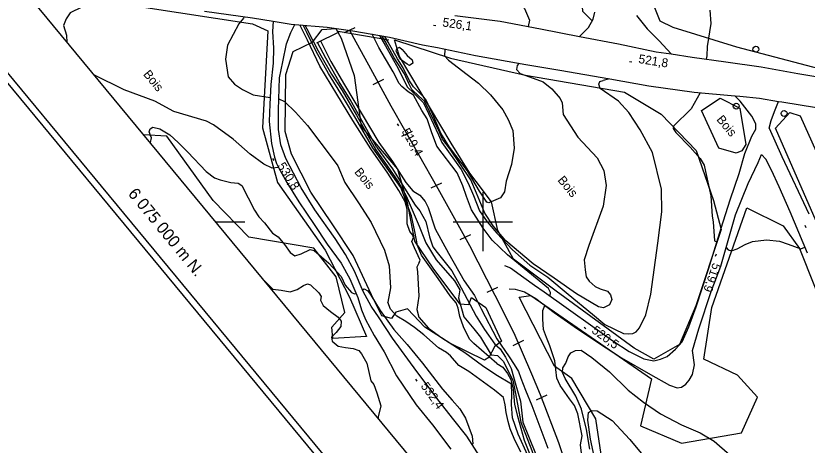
# Model space of a CAD drawing. Extents: x 347312 to 350503, y 6073086 to 6076432.
# Drawn here: x 347542.3 to 347809.5, y 6074924.5 to 6075069.6 of the extents above; entities that cross this region are included whole.
import ezdxf

# ---------------------------------------------------------------- set-up
doc = ezdxf.new("R2010")
doc.units = 0
for name, color, linetype in [('Level 1', 7, 'Continuous'), ('Level 19', 7, 'Continuous'), ('Level 2', 7, 'Continuous'), ('Level 21', 7, 'Continuous'), ('Level 22', 7, 'Continuous'), ('Level 23', 7, 'Continuous'), ('Level 3', 7, 'Continuous'), ('Level 36', 7, 'Continuous'), ('Level 37', 7, 'Continuous'), ('Level 44', 7, 'Continuous'), ('Level 60', 7, 'Continuous'), ('Level 61', 7, 'Continuous')]:
    doc.layers.add(name, color=color, linetype=linetype)

msp = doc.modelspace()

# ---------------------------------------------------------------- linework, layer by layer
at = {"layer": 'Level 1'}
for points in [[(347776.68, 6075071.49), (347777.02, 6075067), (347775.71, 6075059.26)], [(347619.17, 6075068.84), (347617.55, 6075066.91), (347613.79, 6075059.72), (347613.11, 6075054.92), (347613.93, 6075048.96), (347616.11, 6075046.5), (347618.8, 6075044.72), (347622.43, 6075042.93), (347628.18, 6075042.02)], [(347619.41, 6075069.3), (347619.17, 6075068.84)], [(347676.54, 6075042.79), (347674.76, 6075043.96), (347672.59, 6075045.73), (347671.74, 6075046.74), (347669.74, 6075050.69), (347664.91, 6075058.9), (347662.61, 6075063.39)], [(347645.18, 6075061.13), (347648.65, 6075054.15), (347653.21, 6075046.25), (347664.87, 6075026.78), (347669.47, 6075020.39), (347673.93, 6075013.22), (347676.38, 6075010.48), (347678.72, 6075008.98), (347680.56, 6075006.8), (347681.55, 6075004.84), (347683.83, 6074997.57), (347688.41, 6074989.31), (347693.71, 6074980.05), (347697.12, 6074975.06), (347699.43, 6074970.6), (347704.69, 6074960.4), (347708.83, 6074954.28), (347710.61, 6074951.78), (347712, 6074949.34), (347712.87, 6074947.11), (347714.38, 6074943.08), (347716.56, 6074937.87), (347721.93, 6074923.47)], [(347775.71, 6075059.26), (347775.59, 6075056.11), (347775.41, 6075054.99)], [(347773.33, 6075043.59), (347770.36, 6075038.18), (347764.36, 6075032.34), (347764.3, 6075031.5), (347765.2, 6075030.13), (347770, 6075025.24), (347773.43, 6075021.34), (347774.76, 6075019.13), (347775.23, 6075017), (347776.99, 6075008.78), (347777.41, 6075001.82), (347777.76, 6074999.99), (347778.25, 6074993.54), (347779.06, 6074993.15)], [(347631.06, 6075041.57), (347633.05, 6075040.61), (347636.67, 6075037.07), (347640.77, 6075032.47), (347649.49, 6075021.04), (347650.97, 6075018.94), (347653.34, 6075013.2), (347657.94, 6075006.36), (347662.26, 6074999.68), (347666.78, 6074990.41), (347668.35, 6074985.11), (347668.79, 6074977.7), (347667.87, 6074972.83)], [(347722.77, 6074974.78), (347722.86, 6074976.02), (347722.11, 6074977.38), (347715.21, 6074983.17), (347708.3, 6074988.82), (347703.15, 6074993.81), (347700.08, 6074997.76), (347696.12, 6075004.01), (347694.48, 6075008.49), (347693.27, 6075012.13), (347691.32, 6075016.48), (347684.48, 6075025.51), (347682.65, 6075030.36), (347681.15, 6075034.82), (347679.36, 6075037.57), (347676.54, 6075042.79)], [(347782.15, 6074991.29), (347782.89, 6074990.46), (347783.95, 6074990.15), (347785.89, 6074990.85), (347788.62, 6074992.34), (347791.01, 6074993.29), (347795.84, 6074993.88), (347800.21, 6074993.43), (347803.09, 6074992.39), (347807.38, 6074990.88), (347808.79, 6074991.43)], [(347712.78, 6074922.06), (347710.59, 6074926.75), (347709.26, 6074929.93), (347708.49, 6074932.42), (347707.86, 6074935.53), (347707.53, 6074938.11), (347706.97, 6074940.52), (347703.88, 6074943.08), (347695.28, 6074949.34), (347691.86, 6074951.35), (347689.05, 6074954.67), (347687.71, 6074955.79), (347684.96, 6074957.32), (347680.01, 6074961.76), (347676.85, 6074964.25), (347673.93, 6074966.29), (347670.98, 6074968.05), (347668.81, 6074970.46), (347667.87, 6074972.83)], [(347733.3, 6074921.7), (347732.97, 6074924.62), (347733.51, 6074927.6), (347732.12, 6074935.09), (347730.98, 6074937.86), (347729.22, 6074940.1), (347726.05, 6074944.63), (347725.03, 6074947.1), (347724.3, 6074953.01), (347722.63, 6074958), (347721.51, 6074960.82), (347720.49, 6074963.52), (347720.21, 6074967.01), (347720.24, 6074969.97), (347720.94, 6074971.72)]]:
    msp.add_lwpolyline(points, dxfattribs=at)
at = {"layer": 'Level 19'}
for points in [[(347732.67, 6075062.66), (347735.71, 6075065.67), (347737.22, 6075068.49), (347737.84, 6075070.88)], [(347751.92, 6075069.68), (347755.45, 6075065.18), (347759.56, 6075061.15), (347763.54, 6075056.73)], [(347629.21, 6075067.79), (347628.94, 6075064.3), (347629.31, 6075058.61), (347629.18, 6075053.62), (347628.44, 6075046.34), (347628.05, 6075039.79), (347627.83, 6075033.84), (347628.61, 6075026.43), (347629.64, 6075021.82), (347630.25, 6075019.67), (347630.96, 6075018.38), (347633.78, 6075013.22), (347637.86, 6075006.73), (347643.04, 6074999), (347647.4, 6074992.44), (347652.17, 6074985.93), (347655.12, 6074980.7), (347657.73, 6074974.38), (347658.96, 6074970.24), (347660.36, 6074966.98), (347663.32, 6074961.48), (347666.68, 6074956.02), (347670.86, 6074947.92), (347677.45, 6074938.06), (347682.99, 6074931.32), (347689.21, 6074923.15)], [(347699.81, 6074919.34), (347694.59, 6074927.47), (347689.71, 6074933.59), (347685.24, 6074939.31), (347677.66, 6074949.37), (347669.51, 6074960.66), (347664.98, 6074967.51), (347662.32, 6074971.41), (347659.59, 6074976.37), (347656.68, 6074983.32), (347653.64, 6074988.92), (347650.14, 6074994.35), (347643.25, 6075004.04), (347638.61, 6075011.48), (347633.46, 6075021.37), (347631.79, 6075026.04), (347630.92, 6075031.16), (347630.96, 6075037.77), (347631.26, 6075048.67), (347632.44, 6075054.1), (347633.67, 6075060.08), (347635.19, 6075063.94), (347636.53, 6075066.7)], [(347707.25, 6074985.19), (347709.33, 6074984.39), (347713.79, 6074981.1), (347717.39, 6074978.57), (347720.67, 6074976.24), (347728.17, 6074971.01), (347737.97, 6074963.98), (347743.89, 6074959.75), (347749.45, 6074956.12), (347754.34, 6074953.65), (347757.78, 6074953.01), (347759.98, 6074953.58), (347762.22, 6074954.48), (347765.04, 6074956.91), (347767.33, 6074959.34), (347769.59, 6074964.5), (347772.03, 6074971.23), (347776.15, 6074983.99), (347780.53, 6074997.78), (347783.56, 6075007.39), (347786.56, 6075016.24), (347788.43, 6075023.03), (347790.8, 6075028.88), (347792.23, 6075031.27), (347792.23, 6075033.06), (347790.88, 6075035.66), (347786.91, 6075040.78), (347785.04, 6075042.56)], [(347796.73, 6075031.59), (347797.39, 6075034.22), (347798.52, 6075037.25), (347799.17, 6075038.99), (347799.89, 6075040.65)], [(347796.73, 6075031.59), (347800.99, 6075022.01), (347810.06, 6075002.71)], [(347708.87, 6074977.27), (347710.89, 6074977.16), (347714.07, 6074976.31), (347717.89, 6074974.05), (347724.05, 6074969.34), (347731.96, 6074963.79), (347741.62, 6074957.39), (347746.87, 6074953.95), (347756.6, 6074948.35), (347763.02, 6074944.77), (347765.57, 6074943.85), (347767.13, 6074944.03), (347768.57, 6074945.08), (347769.71, 6074946.4), (347770.82, 6074948.37), (347771.52, 6074951.64), (347770.74, 6074956.42), (347772.91, 6074963.83), (347777.15, 6074976.45), (347780.35, 6074984.94), (347782.81, 6074993.63), (347785.35, 6075002.31), (347789.64, 6075012.9), (347793.01, 6075019.96), (347794.13, 6075022.75)], [(347809.66, 6074989.37), (347803.77, 6075003.33), (347800.02, 6075011.84), (347797.52, 6075017.44), (347795.58, 6075021.12), (347794.13, 6075022.75)]]:
    msp.add_lwpolyline(points, dxfattribs=at)
at = {"layer": 'Level 2'}
for points in [[(347693.09, 6075107.08), (347696.94, 6075103.34), (347702.44, 6075093.04), (347704.43, 6075086.79), (347706.07, 6075083.88), (347708.88, 6075077.1), (347712.23, 6075074.08), (347714.07, 6075072.05), (347715.8, 6075068.14), (347715.35, 6075065.99)], [(347729.84, 6075085.22), (347729.61, 6075084.76), (347729.69, 6075083.5), (347732.29, 6075080.61), (347732.83, 6075077.61), (347733.47, 6075074.17), (347733.65, 6075071.14), (347734.85, 6075069.88), (347736.89, 6075067.88)], [(347578.78, 6075075.56), (347576.74, 6075074.61), (347570.99, 6075074), (347564.5, 6075072.51), (347560.66, 6075070.56), (347559.23, 6075068.6), (347558.36, 6075066.29), (347559.36, 6075063.01), (347559.49, 6075060.63)], [(347678.45, 6074986.18), (347678.77, 6074987.03), (347676.86, 6074991.2), (347675.97, 6074993.36), (347676.58, 6074994.67), (347676.36, 6074995.4), (347675.31, 6074996.64), (347674.45, 6074999.23), (347674.45, 6075004.25), (347673.8, 6075006.74), (347671.67, 6075010.51), (347667.86, 6075016.43), (347662.15, 6075024.6), (347656.06, 6075034.16), (347650.73, 6075043.09), (347644.91, 6075052.53), (347640.76, 6075061.36), (347638.18, 6075066.55)], [(347690.93, 6074972.54), (347688.9, 6074974.94), (347684.86, 6074980.82), (347679.25, 6074988.71), (347677.87, 6074991.92), (347676.98, 6074996.73), (347675.85, 6075002), (347672.27, 6075011.58), (347662.81, 6075024.97), (347657.05, 6075034.9), (347652.95, 6075041.92), (347647.85, 6075050.12), (347643.71, 6075057.51), (347640.5, 6075063.93), (347639.29, 6075066.45)], [(347639.92, 6075066.39), (347640.55, 6075065.16), (347644.41, 6075057.8), (347648.88, 6075049.86), (347652.48, 6075044.41), (347657.27, 6075036.07), (347663.82, 6075024.3), (347667.69, 6075018.93), (347671.48, 6075013.35), (347674.12, 6075008.8), (347675.14, 6075006.34), (347675.14, 6075006.34), (347678.44, 6074998.45), (347680.68, 6074992.81), (347684.26, 6074987.1), (347690.38, 6074980.02), (347692.21, 6074976.94), (347691.8, 6074974.22), (347693.61, 6074967.85), (347696.93, 6074963.78), (347699.14, 6074960.95), (347702.83, 6074955.01), (347704.95, 6074954.78), (347706.88, 6074952.82), (347710.13, 6074946.48)], [(347665.11, 6075062.93), (347667.07, 6075059.51), (347671.35, 6075051.8), (347674.45, 6075045.65), (347676.74, 6075043.39), (347680, 6075040.17), (347685.01, 6075029.36)], [(347734.92, 6074981.39), (347735.88, 6074979.94), (347737.89, 6074978.05), (347739.56, 6074977.33), (347742.09, 6074976.53), (347743.14, 6074975.29), (347743.58, 6074973.67), (347742.78, 6074971.94), (347740.71, 6074970.87), (347739.04, 6074971.19), (347731.61, 6074975.57), (347724.05, 6074980.89), (347717.02, 6074985.74), (347707.79, 6074993.52), (347703.46, 6074998.64), (347700.65, 6075002.91), (347697.9, 6075009.62), (347695.97, 6075014.1), (347688.91, 6075024.5), (347686.39, 6075027.95), (347685.36, 6075030.27), (347680.26, 6075040.71), (347678.35, 6075042.39), (347676, 6075044.73), (347675.01, 6075046.72), (347673.48, 6075050), (347670.03, 6075055.44), (347666.96, 6075061.06), (347665.99, 6075062.77)], [(347707.91, 6075013.66), (347707.28, 6075010.07), (347705.98, 6075008.08), (347702.03, 6075006.38), (347701.28, 6075006.63), (347698.85, 6075010.29), (347694.75, 6075017.17), (347688.74, 6075025.24), (347685.85, 6075029.97), (347683.07, 6075036.21), (347680.69, 6075041.32), (347679.83, 6075042.35), (347676.54, 6075045.65), (347675.26, 6075047.67), (347673.11, 6075052.03), (347671.12, 6075055.06), (347667.98, 6075060.75), (347666.91, 6075062.6)], [(347664.23, 6075025.11), (347655.16, 6075041.35), (347651.44, 6075047.25), (347646.91, 6075055.28), (347644.16, 6075060.62)], [(347674.47, 6075056.13), (347676.09, 6075054.67), (347676.35, 6075053.55), (347675.25, 6075052.79), (347674.42, 6075053.3), (347672.07, 6075054.97), (347670.71, 6075057.61), (347670.96, 6075058.58), (347671.8, 6075059.01), (347672.69, 6075058.27), (347674.47, 6075056.13)], [(347687.16, 6075058.27), (347687.03, 6075056.1), (347688.37, 6075054.66), (347694.74, 6075049.76), (347698.51, 6075046.85), (347702.62, 6075042.89), (347706.7, 6075037.83), (347708.52, 6075034.52), (347710.15, 6075030.8), (347710.53, 6075024.85), (347709.64, 6075019.33), (347707.91, 6075013.66)], [(347712.19, 6075053.53), (347711.63, 6075052.79), (347711.3, 6075051.45), (347712.63, 6075050.05), (347715.71, 6075048.92), (347720.4, 6075047.29), (347723.31, 6075044.95), (347726.06, 6075041.69), (347726.8, 6075040.19), (347727.11, 6075036.21)], [(347742.5, 6075048.39), (347742.31, 6075048.15), (347740.68, 6075047.72)], [(347685.01, 6075029.36), (347686.1, 6075026.82), (347692.69, 6075017.61), (347695.05, 6075013.08), (347696.86, 6075008.89), (347698.88, 6075003.67), (347701.46, 6074999.99), (347704.68, 6074996.18), (347710.05, 6074990.46), (347715.9, 6074985.27), (347721.99, 6074981.22), (347728.81, 6074975.51), (347736.98, 6074968.69), (347741.24, 6074965.22), (347747.49, 6074962.23), (347749.07, 6074962.1), (347750.66, 6074962.26), (347751.81, 6074962.8), (347752.86, 6074964.08), (347755.05, 6074968.57), (347756.73, 6074975.56), (347759.13, 6074992.7), (347760.47, 6075003.39), (347760.32, 6075010.96), (347757.26, 6075023.39), (347753.07, 6075031.02), (347749.24, 6075036.97), (347745.8, 6075040.72), (347739.66, 6075045), (347739.14, 6075046.55), (347739.5, 6075047.39), (347740.68, 6075047.72)], [(347727.11, 6075036.21), (347732.09, 6075028.59), (347738.57, 6075021.56), (347740.81, 6075017.34), (347741.67, 6075012.23), (347740.64, 6075005.28), (347735.82, 6074991.96), (347734.25, 6074987.06), (347734.54, 6074983.73), (347734.92, 6074981.39)], [(347587.67, 6075026.53), (347587.8, 6075026.77), (347588.09, 6075028.33), (347587.34, 6075030.36), (347587.66, 6075031.42), (347588.58, 6075031.91), (347590.87, 6075031.4), (347594.32, 6075029.33), (347597.14, 6075026.75), (347600.35, 6075023.54), (347606.59, 6075017.01), (347609.31, 6075014.86), (347611.28, 6075014.1), (347614.92, 6075013.24), (347617.32, 6075013.08), (347618.56, 6075012.24), (347622.87, 6075003.86), (347624.34, 6075001.61), (347626.27, 6074999.62), (347628.98, 6074996.16), (347630.88, 6074994.85), (347632.96, 6074992.24), (347634.95, 6074989.56), (347636.52, 6074988.5), (347638.65, 6074989.1), (347641.65, 6074990.56), (347643.07, 6074990.29), (347648.02, 6074986), (347652.09, 6074981.5), (347653.49, 6074978.59), (347655.64, 6074976.05), (347656.68, 6074975.6), (347657.16, 6074975.75)], [(347664.23, 6075025.11), (347669.47, 6075017.82), (347674.12, 6075010.42), (347677.11, 6075005.63), (347678.76, 6075003.68), (347680.76, 6075000.05), (347682, 6074994.83), (347683.12, 6074991.52), (347684.52, 6074989.56), (347689.52, 6074983.39), (347692.66, 6074977.66), (347697.71, 6074968.03), (347697.71, 6074968.03), (347700.54, 6074963.6), (347704.02, 6074958.62), (347705.87, 6074957.03), (347707.62, 6074954.25), (347709.58, 6074950.38), (347711.12, 6074944.76), (347712.7, 6074939.31), (347713.48, 6074932.27), (347717.79, 6074921.64)], [(347678.45, 6074986.18), (347677.67, 6074984.6), (347677.89, 6074983.07), (347678.34, 6074974.86), (347677.67, 6074970.32), (347678.38, 6074967.75), (347681.67, 6074964.02), (347686.14, 6074960.77), (347693.85, 6074955.73), (347699.82, 6074951.34), (347704.32, 6074948.37), (347709.61, 6074945.24)], [(347625.39, 6074980.88), (347625.5, 6074980.8), (347629.07, 6074977.2), (347631.91, 6074976.81), (347634.88, 6074976.27), (347637.24, 6074977.07), (347639.44, 6074978.38), (347640.78, 6074978.98), (347641.75, 6074978.61), (347644.62, 6074976.01), (347645.36, 6074974.66), (347645.19, 6074973.46), (347646.04, 6074971.67), (347648.52, 6074969.67), (347651.08, 6074967.73), (347652.11, 6074966.36), (347652.03, 6074964.58), (347650.49, 6074962.5), (347648.92, 6074960.92), (347649.09, 6074959.62), (347651.09, 6074957.87), (347653.65, 6074957.51), (347656.2, 6074957.15), (347658.08, 6074956.49), (347659.06, 6074955.33), (347660.8, 6074952.18), (347662.15, 6074946.2), (347663.19, 6074944.97)], [(347659.33, 6074977), (347659.91, 6074977.36), (347661.09, 6074976.65), (347662.18, 6074975.2), (347665.26, 6074970), (347669.88, 6074963.59), (347674.47, 6074958.47), (347679.61, 6074952.23), (347686.33, 6074943.36), (347689.6, 6074939.64), (347692.22, 6074936.7), (347694.18, 6074933.6), (347696.39, 6074927.54), (347696.58, 6074924.94), (347696.32, 6074924.77)], [(347704.7, 6074952.12), (347696.97, 6074958.8), (347695.44, 6074960.29), (347693.41, 6074964.42), (347692.19, 6074967.9), (347691.68, 6074970.77), (347690.93, 6074972.54)], [(347736.13, 6074923.06), (347735.03, 6074929.72), (347733.31, 6074936.64), (347731.36, 6074940.99), (347727.75, 6074947), (347726.84, 6074949.02), (347726.97, 6074950.59), (347728.05, 6074952.16), (347728.78, 6074954.35), (347729.72, 6074955.69), (347731.31, 6074956.49), (347733.2, 6074956.62), (347736.82, 6074954.07), (347742.77, 6074949.24), (347749.11, 6074943), (347754.26, 6074938.95), (347760, 6074935), (347767.13, 6074931.29), (347773.41, 6074928.59), (347778.16, 6074925.8), (347783.4, 6074921.17)], [(347704.7, 6074952.12), (347706.75, 6074950.87), (347708.29, 6074948.67), (347709.4, 6074946.63), (347710.28, 6074943.35), (347710.63, 6074938.16), (347711.68, 6074934.3), (347713.98, 6074926.18), (347716.02, 6074921.06), (347719.17, 6074911.66), (347722.47, 6074903.35), (347723.93, 6074897.15), (347725.45, 6074890.78), (347728.17, 6074884.22), (347729.48, 6074882.56), (347730.24, 6074875.28), (347733.09, 6074862.16), (347734.66, 6074856.85)], [(347663.19, 6074944.97), (347664.24, 6074942.17), (347665.51, 6074937.7), (347664.69, 6074933.98), (347664.61, 6074933.42)], [(347732.99, 6074859.69), (347730.9, 6074868.84), (347728.75, 6074879.28), (347725.79, 6074888.46), (347724.16, 6074893.84), (347720.46, 6074905.43), (347717.74, 6074913.99), (347715.16, 6074920.96), (347711.88, 6074928.13), (347709.98, 6074933.67), (347709.64, 6074938.15), (347709.8, 6074941.73), (347709.61, 6074945.24)], [(347710.13, 6074946.48), (347711.06, 6074941.93), (347712.81, 6074932.19), (347716.48, 6074922.62), (347719.6, 6074913.17), (347722.68, 6074904.3), (347725.14, 6074895.28), (347727.92, 6074887.41), (347730.19, 6074880.96), (347732.48, 6074869.74), (347734.41, 6074860.21), (347736.16, 6074855.31), (347736.67, 6074852.81), (347736.46, 6074851.17), (347735.63, 6074848.22), (347735.72, 6074847.37)], [(347737.55, 6074920.73), (347736.38, 6074926.51), (347735.48, 6074932.92), (347735.68, 6074935.54), (347736.7, 6074936.2), (347738.64, 6074936.11), (347743.71, 6074932.79), (347749.66, 6074926.38), (347755.75, 6074919.02)]]:
    msp.add_lwpolyline(points, dxfattribs=at)
at = {"layer": 'Level 21'}
for points in [[(347606.01, 6075071.15), (347622.21, 6075068.92), (347629.21, 6075067.79), (347635.21, 6075066.82), (347636.53, 6075066.7), (347647.46, 6075065.71), (347656.12, 6075064.57), (347668.44, 6075062.33), (347679.58, 6075059.82), (347684.63, 6075058.92), (347697.53, 6075056.18), (347714.51, 6075053.11), (347726.02, 6075051.26), (347742.92, 6075048.32), (347756.03, 6075045.91), (347771.32, 6075043.76), (347785.04, 6075042.56), (347786.77, 6075042.41), (347793.46, 6075041.73), (347799.89, 6075040.65), (347800.93, 6075040.48), (347818.23, 6075037.65)], [(347690.54, 6075069.7), (347705.83, 6075067.75), (347719.45, 6075065.23), (347732.67, 6075062.66), (347745.79, 6075060.13), (347758.5, 6075057.48), (347763.54, 6075056.73), (347770.69, 6075055.65), (347782.01, 6075054.06), (347794.01, 6075052.37), (347806.38, 6075050.08), (347821.95, 6075047.53), (347837.03, 6075045.32), (347852.37, 6075043.16), (347871.71, 6075040.15), (347874.49, 6075042.05), (347876.01, 6075044), (347876.24, 6075047.77), (347876.48, 6075053.82), (347874.97, 6075059.22), (347871.12, 6075070.29)], [(347668.24, 6075061.4), (347651.15, 6075064.31)]]:
    msp.add_lwpolyline(points, dxfattribs=at)
at = {"layer": 'Level 22'}
msp.add_lwpolyline([(347630.96, 6075018.38), (347628.84, 6075018.09), (347626.02, 6075019.44), (347621.37, 6075022.88), (347615.71, 6075027.9), (347608.98, 6075032.79), (347606.63, 6075034), (347595.65, 6075037.25), (347589.21, 6075040.74), (347578.83, 6075044.58), (347568.57, 6075049.64)], dxfattribs=at)
at = {"layer": 'Level 23'}
for p, q in [((347656.8, 6075065.59), (347653.2, 6075063.85)), ((347666.42, 6075048.02), (347662.81, 6075046.28)), ((347676.15, 6075030.51), (347672.54, 6075028.77)), ((347686.06, 6075013.08), (347682.45, 6075011.34)), ((347695.78, 6074995.56), (347692.17, 6074993.82)), ((347704.95, 6074977.78), (347701.35, 6074976.05)), ((347713.73, 6074959.81), (347710.13, 6074958.08)), ((347721.62, 6074941.41), (347718, 6074939.67))]:
    msp.add_line(p, q, dxfattribs=at)
msp.add_lwpolyline([(347655, 6075064.72), (347657.04, 6075060.79), (347661.39, 6075053.07), (347668.95, 6075039.21), (347678.13, 6075022.92), (347684.83, 6075011.2), (347695.46, 6074992.01), (347704.02, 6074975.2), (347710.42, 6074962.42), (347716.41, 6074948.61), (347719.4, 6074941.62), (347725.57, 6074925.36), (347729.05, 6074914.83), (347732.3, 6074904.57), (347735.57, 6074893.49), (347739.44, 6074879.71), (347744.12, 6074862.2), (347747.29, 6074848.5), (347751.12, 6074833.48), (347752.77, 6074826.72)], dxfattribs=at)
at = {"layer": 'Level 3'}
for p, q in [((347683.37, 6075066.48), (347684.16, 6075066.36)), ((347749.57, 6075054.15), (347750.36, 6075054.03)), ((347671.1, 6075033.12), (347671.49, 6075032.42)), ((347629, 6075021.39), (347629.42, 6075020.71)), ((347808.77, 6074998.8), (347809.06, 6074998.05)), ((347778.74, 6074989.01), (347778.47, 6074988.25)), ((347734.16, 6074964.4), (347734.81, 6074963.93)), ((347677.21, 6074946.79), (347677.68, 6074946.14))]:
    msp.add_line(p, q, dxfattribs=at)
at = {"layer": 'Level 36'}
for centre in [(347792.21, 6075058.32), (347785.56, 6075039.07), (347801.74, 6075036.59)]:
    msp.add_circle(centre, 1, dxfattribs=at)
at = {"layer": 'Level 37'}
msp.add_lwpolyline([(347643.95, 6075060.51), (347651.43, 6075064.24)], dxfattribs=at)
at = {"layer": 'Level 44'}
for points in [[(347544.92, 6075078.26), (347559.71, 6075076.54), (347622.24, 6075066.85), (347627.4, 6075064.54), (347625.58, 6075031.69), (347630.6, 6075013.21), (347646.69, 6074990.37), (347654.9, 6074974.53), (347660.68, 6074961.24), (347649.27, 6074960.5), (347648.94, 6074964.38), (347653.39, 6074969.31), (347650.46, 6074981.32), (347642.95, 6074991.09), (347620.93, 6074994.8), (347608.9, 6075007.16), (347593.29, 6075028.96), (347585.3, 6075029.39)], [(347759.87, 6075067.81), (347755.77, 6075078.09)], [(347866.22, 6075072.03), (347865.65, 6075066.62), (347865.37, 6075057.26), (347869.96, 6075052.12), (347876.09, 6075046.92), (347875.58, 6075044.84), (347872.78, 6075041.91), (347817.9, 6075050.53), (347785.78, 6075058.96), (347764.27, 6075065.62), (347759.87, 6075067.81)], [(347700.55, 6074953.21), (347688.8, 6074958.96), (347680.41, 6074964.4), (347674.52, 6074970.58), (347670.62, 6074969.4), (347669.14, 6074967.28), (347665.85, 6074968.22), (347663.19, 6074973.57), (347656.15, 6074988.58), (347649.38, 6074998.94), (347641.88, 6075009.99), (347635.34, 6075022.82), (347633.22, 6075030.51), (347633.45, 6075049.74), (347635.88, 6075057.54), (347642.45, 6075060.66), (347645.67, 6075064.98), (347650.38, 6075065.36), (347652.11, 6075062.06), (347656.5, 6075049.46), (347658.89, 6075032.17), (347671.22, 6075017.72), (347674.4, 6075006.44), (347676.94, 6074993.44), (347683.06, 6074984.32), (347692.14, 6074972.18), (347695.28, 6074971.97), (347696.14, 6074974.33), (347701.03, 6074970.96), (347706.27, 6074959.67), (347703.9, 6074957.69), (347702.03, 6074954.05), (347700.55, 6074953.21)], [(347710.33, 6074987.28), (347705.07, 6074997.02), (347702.95, 6075006.68), (347697.76, 6075013.62), (347695.59, 6075016.4), (347689.24, 6075026.52), (347671.87, 6075055.89), (347670.19, 6075061.45), (347689.1, 6075055.3), (347714.37, 6075049.54), (347747.86, 6075043.77), (347760.26, 6075036.39), (347771.98, 6075024.12), (347777.92, 6075007.16), (347780.53, 6074997.41), (347771.93, 6074971.61), (347766.36, 6074958.46), (347757.7, 6074953.48), (347751.1, 6074957.24), (347724.76, 6074976.57), (347710.33, 6074987.28)], [(347785.5, 6075023.13), (347779.72, 6075024.88), (347773.89, 6075037.6), (347780.12, 6075041.76), (347786.8, 6075038.39), (347788.86, 6075026.08), (347787.45, 6075024.01), (347785.5, 6075023.13)], [(347812.57, 6075000.14), (347798.85, 6075031.62), (347803.72, 6075036.88), (347807.2, 6075035.75), (347816.53, 6075014.89)], [(347741.98, 6074907.79), (347738.16, 6074933.36), (347730.01, 6074947.04), (347724.22, 6074951.13), (347712.21, 6074974.47), (347716.17, 6074975.09), (347757, 6074946.85), (347753.28, 6074930.95), (347767.03, 6074925.16), (347787.31, 6074928.68), (347792.79, 6074940.69), (347785.99, 6074948.13), (347774.63, 6074953.54), (347777.35, 6074971), (347789.18, 6075004.71), (347801.47, 6074998.55), (347806.96, 6074990.9), (347817.28, 6074964.93)]]:
    msp.add_lwpolyline(points, dxfattribs=at)
at = {"layer": 'Level 60'}
msp.add_line((347609.59, 6075000), (347619.59, 6075000), dxfattribs=at)
for points in [[(349159.76, 6073089.49), (347315.28, 6075321.63), (348655.04, 6076428.72), (350499.52, 6074196.58)], [(348779.44, 6073584.28), (350085.28, 6074663.34), (348652.09, 6076397.74), (347346.25, 6075318.68)]]:
    msp.add_lwpolyline(points, close=True, dxfattribs=at)
msp.add_lwpolyline([(347312.14, 6075321.93), (349159.46, 6073086.35)], dxfattribs=at)
at = {"layer": 'Level 61'}
for p, q in [((347700, 6075010), (347700, 6074990)), ((347690, 6075000), (347710, 6075000))]:
    msp.add_line(p, q, dxfattribs=at)

# ---------------------------------------------------------------- texts
at = {"layer": 'Level 3'}
for s, rotation, p in [('526,1', 351.7558, (347686.21, 6075066.03)), ('521,8', 350.9534, (347752.4, 6075053.67)), ('519,4', 299.1961, (347672.47, 6075030.59)), ('530,8', 301.6879, (347630.48, 6075018.92)), ('519,9', 250.5516, (347777.75, 6074986.3)), ('520,5', 324.0157, (347736.47, 6074962.68)), ('532,4', 305.5692, (347678.86, 6074944.43))]:
    msp.add_text(s, height=3, rotation=rotation, dxfattribs=at).set_placement(p)
at = {"layer": 'Level 44'}
for p in [(347585.12, 6075049.76), (347778.73, 6075034.48), (347656.42, 6075016.73), (347725.06, 6075013.97)]:
    msp.add_text('Bois', height=3, rotation=309.568, dxfattribs=at).set_placement(p)
at = {"layer": 'Level 61'}
msp.add_text('6 075 000 m N.', height=4, rotation=309.3644, dxfattribs=at).set_placement((347579.96, 6075009.36))

doc.saveas('drawing.dxf')
